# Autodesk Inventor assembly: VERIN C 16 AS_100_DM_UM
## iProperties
Shininess: 41.0
Angle Display Precision: 2
Document Length Units: 11269
Document Angle Units: 11279
Document Time Units: 11290
Document Mass Units: 11283
Document Length Units Precision: 3
Document Angle Units Precision: 2
Created: 2002-02
Part Number: VERIN C 16 AS_100_DM_UM
Catalog Web Link: www.traceparts.com
Description: Vérin double effet, type C-AS, amortissement élastique, alésage de 16mm
Vendor: ASCO JOUCOMATIC
Document SubType Name: Assemblage
Designer: Administrateur
Density: 0.0
Volumn: 0.0
Area: 0.0
PropertySet Name: Model Information
Control State: 0
Master: False
Checked Out: False
Author: Administrateur
